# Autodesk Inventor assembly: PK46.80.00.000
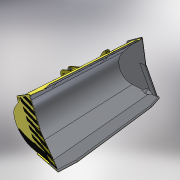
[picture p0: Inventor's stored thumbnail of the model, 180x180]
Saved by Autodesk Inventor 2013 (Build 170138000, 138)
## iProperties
Shininess: 64.0
Length Units: 11269
Angle Units: 11279
Time Units: 11290
Mass Units: 11283
Length Display Precision: 3
Angle Display Precision: 2
Compacted: True
Created: 2005-01
Part Number: PK46.80.00.000
Document SubType Name: Assembly
Designer: SAlex
Manufacturer: Standard
Standards Organization: Custom
Density: 0.0
Volumn: 0.0
Area: 0.0
PropertySet Name: Model Information
Control State: 0
Master: False
Checked Out: False
Author: SAlex
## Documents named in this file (20)
- C:\Product Design Suite 2013 Test Drive\Dynamic Simulation\Workspace\Assy, Chassis, Front\PK46.80.00.000.iam
- C:\Product Design Suite 2013 Test Drive\Dynamic Simulation\Workspace\Assy, Chassis, Front\PK46.80.00.001.ipt
- C:\Product Design Suite 2013 Test Drive\Dynamic Simulation\Workspace\Assy, Chassis, Front\PK46.80.00.010.iam
- C:\Product Design Suite 2013 Test Drive\Dynamic Simulation\Workspace\Assy, Chassis, Front\PK46.80.00.030.iam
- C:\Product Design Suite 2013 Test Drive\Dynamic Simulation\Workspace\Assy, Chassis, Front\PK46.80.00.021.ipt
- C:\Product Design Suite 2013 Test Drive\Dynamic Simulation\Workspace\Assy, Chassis, Front\PK46.80.00.007.ipt
- C:\Product Design Suite 2013 Test Drive\Dynamic Simulation\Workspace\Assy, Chassis, Front\PK46.80.00.005.ipt
- C:\Product Design Suite 2013 Test Drive\Dynamic Simulation\Workspace\Assy, Chassis, Front\PK46.80.00.008.ipt
- C:\Product Design Suite 2013 Test Drive\Dynamic Simulation\Workspace\Assy, Chassis, Front\PK46.80.00.009.ipt
- C:\Product Design Suite 2013 Test Drive\Dynamic Simulation\Workspace\Assy, Chassis, Front\PK46.80.00.003.ipt
- C:\Product Design Suite 2013 Test Drive\Dynamic Simulation\Workspace\Assy, Chassis, Front\PK46.80.00.004.ipt
- C:\Product Design Suite 2013 Test Drive\Dynamic Simulation\Workspace\Assy, Chassis, Front\PK46.80.00.002.ipt
- C:\Product Design Suite 2013 Test Drive\Dynamic Simulation\Workspace\Assy, Chassis, Front\PK46.80.00.006.ipt
- C:\Product Design Suite 2013 Test Drive\Dynamic Simulation\Workspace\Assy, Chassis, Front\PK46.80.00.025.ipt
- C:\Product Design Suite 2013 Test Drive\Dynamic Simulation\Workspace\Assy, Chassis, Front\PK46.80.00.026.ipt
- C:\Product Design Suite 2013 Test Drive\Dynamic Simulation\Workspace\Assy, Chassis, Front\PK46.80.00.050.iam
- C:\Product Design Suite 2013 Test Drive\Dynamic Simulation\Workspace\Assy, Chassis, Front\PK46.80.00.031-1.ipt
- C:\Product Design Suite 2013 Test Drive\Dynamic Simulation\Workspace\Assy, Chassis, Front\PK46.80.00.030_MIR1.iam
- C:\Product Design Suite 2013 Test Drive\Dynamic Simulation\Workspace\Assy, Chassis, Front\PK46.21.01.094.ipt
- C:\Product Design Suite 2013 Test Drive\Dynamic Simulation\Workspace\Assy, Chassis, Front\PK46.21.01.095.ipt
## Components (28 placed, 19 different names)
1. PK46.80.00.001:1 — Совмещение:2, Заподлицо:2, Заподлицо:3, Совмещение:6, Совмещение:7, Совмещение:8, Совмещение:10, Совмещение:16, Совмещение:17, Совмещение:19, Совмещение:44, Совмещение:45, Совмещение:46, Совмещение:32, Заподлицо:26, Заподлицо:27, Угол:2, Совмещение:50, Касательность:1, Совмещение:52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
2. PK46.80.00.010:1 [sub-assembly] — Совмещение:7, Заподлицо:6, Заподлицо:7, Совмещение:25, Заподлицо:18, Совмещение:42, Совмещение:43, Касательность:1, Совмещение:55
3. PK46.80.00.030:1 [sub-assembly] — Совмещение:2, Совмещение:18, Совмещение:33, Совмещение:36, Совмещение:63, Совмещение:64
4. PK46.80.00.021:1 — Заподлицо:2, Заподлицо:3, Совмещение:6, Совмещение:9, Совмещение:11, Заподлицо:14, Совмещение:20, Заподлицо:15, Mate:67
5. PK46.80.00.007:1 — Совмещение:8, Заподлицо:6, Совмещение:9, Совмещение:12, Совмещение:13, Angle, Совмещение:21, Заподлицо:16
6. PK46.80.00.007:2 — Совмещение:10, Совмещение:11, Заподлицо:7, Совмещение:14, Совмещение:15, Совмещение:22
7. PK46.80.00.005:1 — Совмещение:12, Заподлицо:8, Заподлицо:9, Заподлицо:12, Заподлицо:13, Совмещение:16, Angle, Совмещение:23
8. PK46.80.00.005:2 — Совмещение:13, Заподлицо:8, Заподлицо:9
9. PK46.80.00.005:3 — Совмещение:14, Заподлицо:10, Заподлицо:11, Заподлицо:12, Заподлицо:13, Совмещение:24
10. PK46.80.00.005:4 — Совмещение:15, Заподлицо:10, Заподлицо:11
11. PK46.80.00.008:1 — Совмещение:17, Заподлицо:14, Совмещение:18
12. PK46.80.00.008:2 — Совмещение:19, Совмещение:20, Заподлицо:15
13. PK46.80.00.009:1 — Совмещение:21, Совмещение:23, Заподлицо:16, Заподлицо:17
14. PK46.80.00.009:2 — Совмещение:22, Заподлицо:17, Совмещение:24
15. PK46.80.00.003:1 — Совмещение:25, Заподлицо:18, Совмещение:52, Совмещение:54
16. PK46.80.00.002:1 — Совмещение:33, Совмещение:32, Угол:2, Совмещение:50, Совмещение:57, Mate:66, Mate:68
17. PK46.80.00.006:1 — Заподлицо:22, Заподлицо:23
18. PK46.80.00.006:2 — Заподлицо:22, Заподлицо:23, Совмещение:36
19. PK46.80.00.004:1 — Совмещение:43, Совмещение:44, Заподлицо:25
20. PK46.80.00.004:2 — Совмещение:42, Совмещение:45, Заподлицо:25, Совмещение:46
21. PK46.80.00.025:1 — Совмещение:54, Совмещение:55, Совмещение:56, Вставка:1
22. PK46.80.00.026:1 — Совмещение:57, Совмещение:58
23. PK46.80.00.050:1 [sub-assembly] — Вставка:1, Совмещение:58
24. PK46.80.00.031-1:1 — Заподлицо:28
25. PK46.80.00.031-1:2 — Совмещение:63, Совмещение:64, Заподлицо:28
26. PK46.80.00.030_MIR1:1 [sub-assembly]
27. PK46.21.01.094:1
28. PK46.21.01.095:1
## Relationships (66: Mate 41, Flush 21, Angle 2, Tangent 1, Insert 1)
- Совмещение:2 [Mate]: PK46.80.00.001:1 ↔ PK46.80.00.030:1
- Заподлицо:2 [Flush]: PK46.80.00.001:1 ↔ PK46.80.00.021:1
- Заподлицо:3 [Flush]: PK46.80.00.001:1 ↔ PK46.80.00.021:1
- Совмещение:6 [Mate]: PK46.80.00.001:1 ↔ PK46.80.00.021:1
- Совмещение:7 [Mate]: PK46.80.00.001:1 ↔ PK46.80.00.010:1
- Совмещение:8 [Mate]: PK46.80.00.001:1 ↔ PK46.80.00.007:1
- Заподлицо:6 [Flush]: PK46.80.00.010:1 ↔ PK46.80.00.007:1
- Совмещение:9 [Mate]: PK46.80.00.021:1 ↔ PK46.80.00.007:1
- Совмещение:10 [Mate]: PK46.80.00.001:1 ↔ PK46.80.00.007:2
- Совмещение:11 [Mate]: PK46.80.00.021:1 ↔ PK46.80.00.007:2
- Заподлицо:7 [Flush]: PK46.80.00.010:1 ↔ PK46.80.00.007:2
- Совмещение:12 [Mate]: PK46.80.00.007:1 ↔ PK46.80.00.005:1
- Совмещение:13 [Mate]: PK46.80.00.007:1 ↔ PK46.80.00.005:2
- Совмещение:14 [Mate]: PK46.80.00.007:2 ↔ PK46.80.00.005:3
- Совмещение:15 [Mate]: PK46.80.00.007:2 ↔ PK46.80.00.005:4
- Заподлицо:8 [Flush]: PK46.80.00.005:1 ↔ PK46.80.00.005:2
- Заподлицо:9 [Flush]: PK46.80.00.005:1 ↔ PK46.80.00.005:2
- Заподлицо:10 [Flush]: PK46.80.00.005:3 ↔ PK46.80.00.005:4
- Заподлицо:11 [Flush]: PK46.80.00.005:3 ↔ PK46.80.00.005:4
- Заподлицо:12 [Flush]: PK46.80.00.005:1 ↔ PK46.80.00.005:3
- Заподлицо:13 [Flush]: PK46.80.00.005:1 ↔ PK46.80.00.005:3
- Совмещение:16 [Mate]: PK46.80.00.001:1 ↔ PK46.80.00.005:1
- Angle: PK46.80.00.007:1 ↔ PK46.80.00.005:1
- Совмещение:17 [Mate]: PK46.80.00.001:1 ↔ PK46.80.00.008:1
- Заподлицо:14 [Flush]: PK46.80.00.021:1 ↔ PK46.80.00.008:1
- Совмещение:18 [Mate]: PK46.80.00.030:1 ↔ PK46.80.00.008:1
- Совмещение:19 [Mate]: PK46.80.00.001:1 ↔ PK46.80.00.008:2
- Совмещение:20 [Mate]: PK46.80.00.021:1 ↔ PK46.80.00.008:2
- Заподлицо:15 [Flush]: PK46.80.00.021:1 ↔ PK46.80.00.008:2
- Совмещение:21 [Mate]: PK46.80.00.007:1 ↔ PK46.80.00.009:1
- Совмещение:22 [Mate]: PK46.80.00.007:2 ↔ PK46.80.00.009:2
- Совмещение:23 [Mate]: PK46.80.00.005:1 ↔ PK46.80.00.009:1
- Заподлицо:16 [Flush]: PK46.80.00.007:1 ↔ PK46.80.00.009:1
- Заподлицо:17 [Flush]: PK46.80.00.009:1 ↔ PK46.80.00.009:2
- Совмещение:24 [Mate]: PK46.80.00.005:3 ↔ PK46.80.00.009:2
- Совмещение:25 [Mate]: PK46.80.00.010:1 ↔ PK46.80.00.003:1
- Заподлицо:18 [Flush]: PK46.80.00.010:1 ↔ PK46.80.00.003:1
- Совмещение:33 [Mate]: PK46.80.00.030:1 ↔ PK46.80.00.002:1
- Заподлицо:22 [Flush]: PK46.80.00.006:1 ↔ PK46.80.00.006:2
- Заподлицо:23 [Flush]: PK46.80.00.006:1 ↔ PK46.80.00.006:2
- Совмещение:36 [Mate]: PK46.80.00.030:1 ↔ PK46.80.00.006:2
- Совмещение:42 [Mate]: PK46.80.00.010:1 ↔ PK46.80.00.004:2
- Совмещение:43 [Mate]: PK46.80.00.010:1 ↔ PK46.80.00.004:1
- Совмещение:44 [Mate]: PK46.80.00.001:1 ↔ PK46.80.00.004:1
- Совмещение:45 [Mate]: PK46.80.00.001:1 ↔ PK46.80.00.004:2
- Заподлицо:25 [Flush]: PK46.80.00.004:1 ↔ PK46.80.00.004:2
- Совмещение:46 [Mate]: PK46.80.00.001:1 ↔ PK46.80.00.004:2
- Совмещение:32 [Mate]: PK46.80.00.001:1 ↔ PK46.80.00.002:1
- Заподлицо:26 [Flush]: PK46.80.00.001:1
- Заподлицо:27 [Flush]: PK46.80.00.001:1
- Угол:2 [Angle]: PK46.80.00.001:1 ↔ PK46.80.00.002:1
- Совмещение:50 [Mate]: PK46.80.00.001:1 ↔ PK46.80.00.002:1
- Касательность:1 [Tangent]: PK46.80.00.001:1 ↔ PK46.80.00.010:1
- Совмещение:52 [Mate]: PK46.80.00.001:1 ↔ PK46.80.00.003:1
- Совмещение:54 [Mate]: PK46.80.00.003:1 ↔ PK46.80.00.025:1
- Совмещение:55 [Mate]: PK46.80.00.010:1 ↔ PK46.80.00.025:1
- Совмещение:56 [Mate]: PK46.80.00.001:1 ↔ PK46.80.00.025:1
- Вставка:1 [Insert]: PK46.80.00.025:1 ↔ PK46.80.00.050:1
- Совмещение:57 [Mate]: PK46.80.00.002:1 ↔ PK46.80.00.026:1
- Совмещение:58 [Mate]: PK46.80.00.026:1 ↔ PK46.80.00.050:1
- Совмещение:63 [Mate]: PK46.80.00.030:1 ↔ PK46.80.00.031-1:2
- Совмещение:64 [Mate]: PK46.80.00.030:1 ↔ PK46.80.00.031-1:2
- Заподлицо:28 [Flush]: PK46.80.00.031-1:1 ↔ PK46.80.00.031-1:2
- Mate:66: PK46.80.00.002:1
- Mate:67: PK46.80.00.021:1
- Mate:68: PK46.80.00.002:1
